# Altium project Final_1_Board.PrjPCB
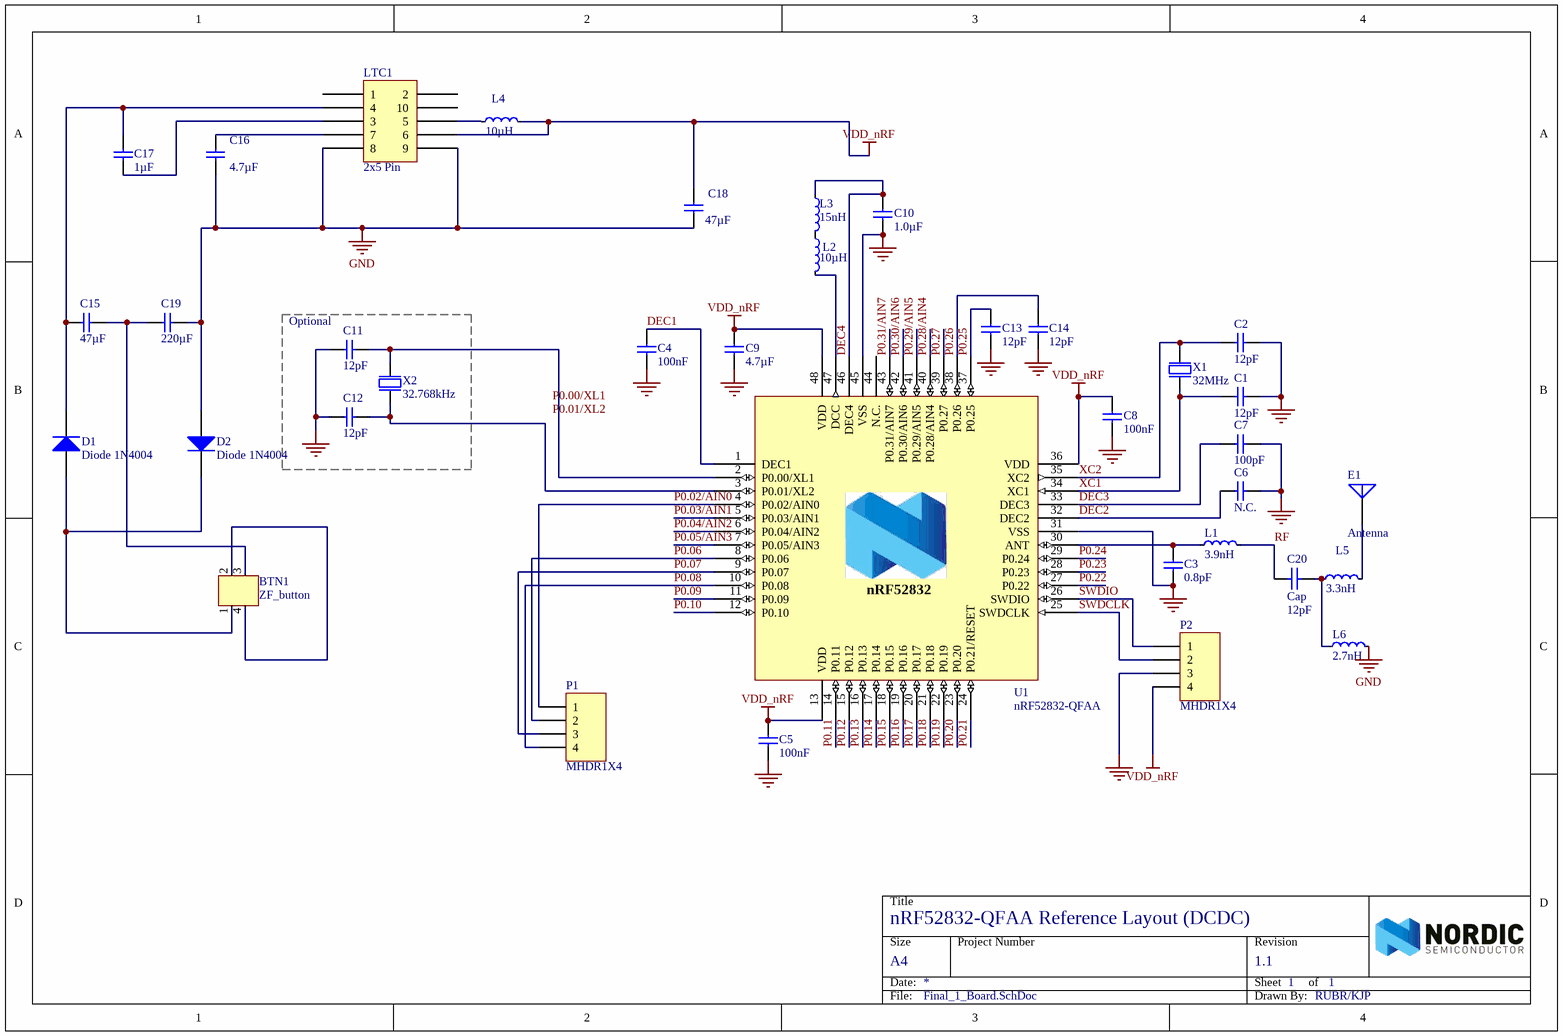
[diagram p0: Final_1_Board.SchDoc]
1 sheet, 36 parts. Net scope: global (net labels, ports and power ports of the same name join across sheets).
Board file: Final_1_Board.PcbDoc

## Sheet Final_1_Board.SchDoc: nRF52832-QFAA Reference Layout (DCDC)
size A4; Revision: 1.1; SheetNumber: 1; SheetTotal: 1; DrawnBy: RUBR/KJP; DocumentSize: A4; PCAName: nRF52832-QFAA Reference Layout (DCDC)

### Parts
BTN1  ZF_button  [ZF-button]
C1  12pF  [CAPC1005X04L]
C2  12pF  [CAPC1005X04L]
C3  0.8pF  [CAPC1005X04L]
C4  100nF  [CAPC1005X04L]
C5  100nF  [CAPC1005X04L]
C6  N.C.  [CAPC1005X04L]
C7  100pF  [CAPC1005X04L]
C8  100nF  [CAPC1005X04L]
C9  4.7µF  [CAPC1608X06L]
C10  1.0µF  [CAPC1608X06L]
C11  12pF  [CAPC1005X04L]
C12  12pF  [CAPC1005X04L]
C13  12pF  [CAPC1005X04L]
C14  12pF  [CAPC1005X04L]
C15  47µF  [C1210]
C16  4.7µF  [CAPC1608X06L]
C17  1µF  [CAPC1608X06L]
C18  47µF  [CAPC1608X06L]
C19  220µF  [C1210]
C20  Cap  value 12pF  [0402]
D1  Diode 1N4004  [SOT-23_N]
D2  Diode 1N4004  [SOT-23_N]
E1  Antenna  [antenne]
L1  3.9nH  [INDC1005X04L]
L2  10µH  [INDC1608X06L]
L3  15nH  [INDC1005X04L]
L4  10µH  [INDC1608X06L]
L5  3.3nH  [0402]
L6  2.7nH  [0402]
LTC1  2x5 Pin  [MSOP10 - duplicate1]
P1  MHDR1X4  [MHDR1X4]
P2  MHDR1X4  [MHDR1X4]
U1  nRF52832-QFAA  [QFN40P600X600X90-48N]
X1  32MHz  [BT-XTAL_2016]
X2  32.768kHz  [XTAL_3215]

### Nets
GND: C1.2 C2.2 C3.1 C4.2 C5.2 C6.1 C7.2 C8.2 C9.2 C10.1 C11.2 C12.2 C13.2 C14.2 C16.1 C18.1 C19.1 D2.1(A) L6.2 LTC1.8 LTC1.9 P2.3 U1.31(VSS) U1.45(VSS) U1.49(GND) X1.2(GND) X1.4(GND)
VDD_nRF: C5.1 C8.1 C9.1 C18.2 L4.2 LTC1.6 P2.4 U1.13(VDD) U1.36(VDD) U1.48(VDD)
DEC1: C4.1 U1.1(DEC1)
DEC2: C6.2 U1.32(DEC2)
DEC3: C7.1 U1.33(DEC3)
DEC4: C10.2 L3.1 U1.46(DEC4)
P0.02/AIN0: P1.1 U1.4(P0.02/AIN0)
P0.03/AIN1: U1.5(P0.03/AIN1)
P0.04/AIN2: U1.6(P0.04/AIN2)
P0.05/AIN3: U1.7(P0.05/AIN3)
P0.06: P1.2 U1.8(P0.06)
P0.07: P1.3 U1.9(P0.07)
P0.08: P1.4 U1.10(P0.08)
P0.09: U1.11(P0.09)
P0.10: U1.12(P0.10)
P0.11: U1.14(P0.11)
P0.12: U1.15(P0.12)
P0.13: U1.16(P0.13)
P0.14: U1.17(P0.14)
P0.15: U1.18(P0.15)
P0.16: U1.19(P0.16)
P0.17: U1.20(P0.17)
P0.18: U1.21(P0.18)
P0.19: U1.22(P0.19)
P0.20: U1.23(P0.20)
P0.21: U1.24(P0.21/RESET)
P0.22: U1.27(P0.22)
P0.23: U1.28(P0.23)
P0.24: U1.29(P0.24)
P0.25: C13.1 U1.37(P0.25)
P0.26: C14.1 U1.38(P0.26)
P0.27: U1.39(P0.27)
P0.28/AIN4: U1.40(P0.28/AIN4)
P0.29/AIN5: U1.41(P0.29/AIN5)
P0.30/AIN6: U1.42(P0.30/AIN6)
P0.31/AIN7: U1.43(P0.31/AIN7)
RF: C20.1 L1.2
SWDCLK: P2.2 U1.25(SWDCLK)
SWDIO: P2.1 U1.26(SWDIO)
XC1: C1.1 U1.34(XC1) X1.1(inp)
XC2: C2.1 U1.35(XC2) X1.3(out)
NetBTN1_1: BTN1.1 D1.1(A) D2.2(K)
NetBTN1_2: BTN1.2 BTN1.4
NetBTN1_3: BTN1.3 C15.1 C19.2
NetC3_2: C3.2 L1.1 U1.30(ANT)
NetC11_1: C11.1 U1.2(P0.00/XL1) X2.1(inp)
NetC12_1: C12.1 U1.3(P0.01/XL2) X2.2(out)
NetC15_2: C15.2 C17.2 D1.2(K) LTC1.4
NetC16_2: C16.2 LTC1.7
NetC17_1: C17.1 LTC1.3
NetC20_2: C20.2 L5.1 L6.1
NetE1_1: E1.1(A) L5.2
NetL2_1: L2.1 L3.2
NetL2_2: L2.2 U1.47(DCC)
NetL4_1: L4.1 LTC1.5

Not connected (* = marked no-connect by the designer): LTC1 1 2 10; U1 44(N.C.)

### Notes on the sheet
- (near C11) Optional
- Labels drawn without touching a wire or pin: P0.00/XL1, P0.01/XL2

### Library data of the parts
C1 C2 C11-C14 = C0402-12p: Capacitor, NP0, ±2%; Note: 50V; Artikkelnr Noca: 20029159; Artikkelnr Simpro: N.A.
C3 = C0402-0.8p: Capacitor, NP0, ±5%; Note: 50V; Artikkelnr Noca: 20029147; Artikkelnr Simpro: N.A.
C4 C5 C8 = C0402-100n: Capacitor, X7R, ±10%; Note: 16V; Artikkelnr Noca: 20039200; Artikkelnr Simpro: N.A.
C6 = C0402-N.C.: Not mounted; Note: Chip Cap; Artikkelnr Noca: N.A.
C7 = C0402-100p: Capacitor, NP0, ±5%; Note: 50V; Artikkelnr Noca: 20029135; Artikkelnr Simpro: N.A.
C9 = C0603-4µ7: Capacitor, X5R, ±10%; Note: 6.3V; Artikkelnr Noca: 20069060; Artikkelnr Simpro: N.A.
C10 = C0603-1µ0: Capacitor, X7R, ±10%; Note: 16V; Artikkelnr Noca: 20039335; Artikkelnr Simpro: N.A.
C15-C19 = CAP_0603: Capacitor, X5R, ±10%; Part Number: C0603-4µ7; Note: 6.3V; Artikkelnr Noca: 20069060; Artikkelnr Simpro: N.A.
C20 = Cap: Capacitor
D1 D2 = Diode 1N4004: 1 Amp General Purpose Rectifier; pin to pad: 2>3
E1 = Antenna: Generic Antenna
L1 = L0402-3n9: High frequency chip inductor ±5%; Manufacturer: Murata; Manufacturer Part Number: LQP15MN3N9B02D; Artikkelnr Noca: 33029151; Artikkelnr Simpro: N.A.
L2 = L0603-10µ: Chip inductor, IDC,min = 50 mA, ±20%; Manufacturer: Taiyo Yuden; Manufacturer Part Number: LBMF1608T100K; 2nd source part number: 178-6105; Note: LBMF1608T100K 10µH 80mA 0603; Artikkelnr Noca: 33029314; Artikkelnr Simpro: N.A.
L3 = L0402-15n: High frequency chip inductor ±10%; Manufacturer: Taiyo Yuden; Manufacturer Part Number: HK100515NJ-T; 2nd source part number: 658-1328; Artikkelnr Noca: 33029323; Artikkelnr Simpro: N.A.
L4 = IND_0603: Chip inductor, IDC,min = 50 mA, ±20%; Part Number: L0603-10µ; Manufacturer: Taiyo Yuden; Manufacturer Part Number: LBMF1608T100K; 2nd source part number: 178-6105; Note: LBMF1608T100K 10µH 80mA 0603; Artikkelnr Noca: 33029314; Artikkelnr Simpro: N.A.
L5 L6 = L0402-3n9: High frequency chip inductor ±5%; Manufacturer: Murata; Manufacturer Part Number: LQP15MN3N9B02D; Value: 3.9nH; Artikkelnr Noca: 33029151; Artikkelnr Simpro: N.A.
P1 P2 = MHDR1X4: Header, 4-Pin
U1 = nRF52832-QFAA: Multi-protocol Bluetooth Low Energy, ANT and 2.4GHz proprietary system-on-chip; Manufacturer: Nordic Semiconductor; Artikkelnr Noca: N.A.
X1 = XTAL_SMD2016_32MHz_8pF_General: XTAL SMD 2016, 32MHz, Cl=8pF, Total Tol: ±40ppm; Note: XTAL SMD 32.000MHz; Artikkelnr Noca: N.A.
X2 = XTAL_SMD3215_32.768kHz_9pF_General: XTAL SMD 3215, 32.768kHz, Cl=9pF, Total Tol: ±50ppm; Note: XTAL SMD 32.768kHz; Artikkelnr Noca: N.A.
